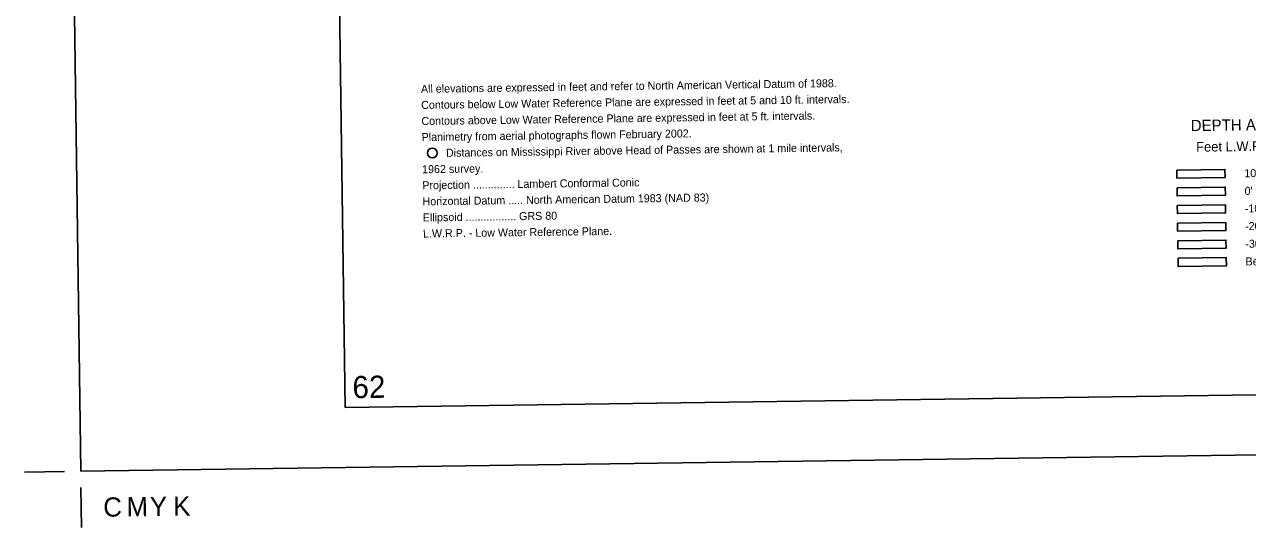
# Model space of a CAD drawing. Extents: x 3767014 to 3805179, y 361544 to 387384.
# Drawn here: x 3767349 to 3780033, y 361544 to 366761 of the extents above; entities that cross this region are included whole.
import ezdxf

# ---------------------------------------------------------------- set-up
doc = ezdxf.new("R2010")
doc.units = 0
for name, color, linetype in [('G-ANNO-NPLT', 7, 'Continuous'), ('V-ANNO-DIMS', 7, 'Continuous'), ('V-ANNO-NOTE', 7, 'Continuous'), ('V-ANNO-SYMB', 7, 'Continuous'), ('V-ANNO-TEXT', 7, 'Continuous'), ('V-TOPO-DPTH', 7, 'Continuous')]:
    doc.layers.add(name, color=color, linetype=linetype)

msp = doc.modelspace()

# ---------------------------------------------------------------- linework, layer by layer
at = {"layer": 'G-ANNO-NPLT'}
msp.add_lwpolyline([(3767932.576, 362127.078), (3804595.706, 362636.374), (3804260.034, 386800.71), (3767596.904, 386291.414)], close=True, dxfattribs=at)
at = {"layer": 'V-ANNO-DIMS'}
for p, q in [((3767765.926, 362124.763), (3767349.299, 362118.976)), ((3767934.891, 361960.428), (3767940.679, 361543.801))]:
    msp.add_line(p, q, dxfattribs=at)
at = {"layer": 'V-ANNO-NOTE'}
msp.add_circle((3771578.804, 365427.167), 50, dxfattribs=at)
at = {"layer": 'V-ANNO-SYMB'}
msp.add_lwpolyline([(3770673.762, 362790.263), (3803753.771, 363249.785), (3803435.463, 386164.149), (3770355.454, 385704.627), (3770673.762, 362790.263)], dxfattribs=at)
at = {"layer": 'V-TOPO-DPTH'}
for points in [[(3779299.685, 365250.35), (3779799.636, 365257.295), (3779800.817, 365172.303), (3779300.865, 365165.358)], [(3779302.226, 365067.368), (3779802.178, 365074.313), (3779803.359, 364989.321), (3779303.407, 364982.376)], [(3779304.768, 364884.385), (3779804.72, 364891.33), (3779805.901, 364806.339), (3779305.949, 364799.394)], [(3779307.31, 364701.403), (3779807.262, 364708.348), (3779808.443, 364623.356), (3779308.491, 364616.411)], [(3779309.852, 364518.421), (3779809.804, 364525.366), (3779810.984, 364440.374), (3779311.033, 364433.429)], [(3779312.394, 364335.438), (3779812.346, 364342.383), (3779813.526, 364257.392), (3779313.575, 364250.447)]]:
    msp.add_lwpolyline(points, close=True, dxfattribs=at)

# ---------------------------------------------------------------- texts
at = {"layer": 'V-ANNO-DIMS'}
for s, p in [('C', (3768168.104, 361655.671)), ('M', (3768409.752, 361659.028)), ('Y', (3768651.399, 361662.385)), ('K', (3768893.046, 361665.741))]:
    msp.add_text(s, height=199.267, rotation=0.7958573, dxfattribs=at).set_placement(p)
at = {"layer": 'V-ANNO-NOTE'}
for s, rotation, p in [('All elevations are expressed in feet and refer to North American Vertical Datum of 1988.', 0.7958642, (3771461.878, 366050.904)), ('Contours below Low Water Reference Plane are expressed in feet at 5 and 10 ft. intervals.', 0.7958642, (3771464.194, 365884.22)), ('Contours above Low Water Reference Plane are expressed in feet at 5 ft. intervals.', 0.7958642, (3771466.509, 365717.536)), ('Planimetry from aerial photographs flown February 2002.', 0.7958642, (3771468.824, 365550.852)), ('Distances on Mississippi River above Head of Passes are shown at 1 mile intervals,', 0.7958642, (3771721.313, 365387.643)), ('1962 survey.', 0.7958642, (3771473.455, 365217.484)), ('Projection .............. Lambert Conformal Conic', 0.7958337, (3771475.77, 365050.819)), ('Horizontal Datum ..... North American Datum 1983 (NAD 83)', 0.7958337, (3771478.086, 364884.135)), ('Ellipsoid ................. GRS 80', 0.7958337, (3771480.402, 364717.451)), ('L.W.R.P. - Low Water Reference Plane.', 0.7958337, (3771482.717, 364550.767))]:
    msp.add_text(s, height=83, rotation=rotation, dxfattribs=at).set_placement(p)
at = {"layer": 'V-ANNO-TEXT'}
msp.add_text('62', height=230, rotation=0.7958583, dxfattribs=at).set_placement((3770751.947, 362884.688))
at = {"layer": 'V-TOPO-DPTH'}
for s, height, rotation, p in [('DEPTH AREAS', 116.7, 0.7958706, (3779444.774, 365654.073)), ('Feet L.W.R.P.', 100, 0.7958589, (3779501.454, 365440.675)), ("10' to 0'", 83, 0.7958589, (3780000.784, 365176.081)), ("0' to -10'", 83, 0.7958589, (3780003.326, 364993.099)), ("-10' to -20'", 83, 0.7958589, (3780005.868, 364810.116)), ("-20' to -30'", 83, 0.7958589, (3780008.409, 364627.134)), ("-30' to -45'", 83, 0.7958589, (3780010.951, 364444.152)), ("Below -45'", 83, 0.7958589, (3780013.493, 364261.169))]:
    msp.add_text(s, height=height, rotation=rotation, dxfattribs=at).set_placement(p)

doc.saveas('drawing.dxf')
